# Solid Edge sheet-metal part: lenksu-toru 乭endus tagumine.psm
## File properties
Author: Stella-Marii
Template: Iso Metric Sheet Metal.psm
Last saved by: Stella-Marii
Revision: 1
Application: Solid Edge
Accuracy: 0,990
Material Thickness: 1,00 mm
Bend Radius: 1,00 mm
Relief Width: 1,00 mm
Relief Length: 0,00 mm
Neutral Factor: 0,330
Minimum Arc Length: 0,10 mm
Deviational Tolerance: 0,10 mm
Username: Stella-Marii
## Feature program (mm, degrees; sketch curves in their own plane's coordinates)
base contour flange "ContourFlange_1"
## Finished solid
Body 1: solid body, 10 faces, 24 edges, 16 vertices.
  Faces by surface: plane 8, cylinder 2
  Edges by curve: line 20, circle 4
Bounding box of the edges (mm): 47.000 x 71.372 x 55.914, from (-23.5, -23.5, 0) to (23.5, 47.8718, 55.9145).
Cylindrical faces by radius (mm): R22.5 x1, R23.5 x1
Planar faces by outward normal: +x 2, +y 2, +z 1, -x 2, -z 1
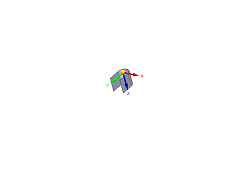
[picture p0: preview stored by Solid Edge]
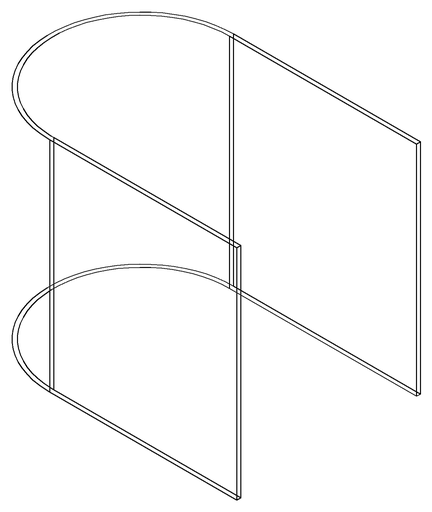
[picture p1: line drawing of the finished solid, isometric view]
